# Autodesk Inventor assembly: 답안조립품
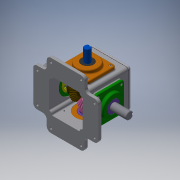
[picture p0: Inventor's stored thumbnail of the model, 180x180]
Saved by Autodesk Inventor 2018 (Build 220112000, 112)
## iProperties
Created: 2019-12
Part Number: 답안조립품
Document SubType Name: Assembly
Designer: Administrator
Author: Administrator
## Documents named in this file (16)
- C:\Users\Administrator\Desktop\391204V1072\답안조립품.iam
- C:\Users\Administrator\Desktop\391204V1072\본체.ipt
- C:\Users\Administrator\Desktop\391204V1072\메인커버.ipt
- C:\Users\Administrator\Desktop\391204V1072\서브커버.ipt
- C:\Users\Administrator\Desktop\391204V1072\베어링 6204.ipt
- C:\Users\Administrator\Desktop\391204V1072\베어링 6203.ipt
- C:\Users\Administrator\Desktop\391204V1072\메인축.ipt
- C:\Users\Administrator\Desktop\391204V1072\Ű 4x4.ipt
- C:\Users\Administrator\Desktop\391204V1072\메인베벨기어.ipt
- C:\Users\Administrator\Desktop\391204V1072\오일 실 20 35 8.ipt
- C:\Users\Administrator\Desktop\391204V1072\서브축.ipt
- C:\Users\Administrator\Desktop\391204V1072\서브베벨기어.ipt
- C:\Users\Administrator\Desktop\391204V1072\오일 실 17 32 8.ipt
- C:\Users\Administrator\Desktop\391204V1072\개스킷.ipt
- C:\Users\Administrator\Desktop\391204V1072\상부커버.ipt
- C:\Users\Administrator\Desktop\391204V1072\볼트 M4.ipt
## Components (5 placed, 2 different names)
1. Ű 4x4:1
2. Ű 4x4:2
3. Ű 4x4:3
4. Ű 4x4:4
5. 개스킷:1
